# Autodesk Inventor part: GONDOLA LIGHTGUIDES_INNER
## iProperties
Shininess: 64.0
Length Units: 11272
Angle Units: 11279
Time Units: 11290
Mass Units: 11286
Length Display Precision: 3
Angle Display Precision: 2
Compacted: True
Part Number: GONDOLA LIGHTGUIDES_INNER
Document SubType Name: Modeling
Created: 2004-08
Designer: John Blackburn
Manufacturer: Standard
Standards Organization: Custom
Material: Lexan, Clear
Density: 0.0
Volumn: 0.0
Area: 0.0
PropertySet Name: Model Information
Control State: 0
Master: False
Checked Out: False
Author: John Blackburn
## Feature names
1. Base1
